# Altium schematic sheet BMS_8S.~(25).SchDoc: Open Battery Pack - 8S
size A4; Author: Morgane Vallée; Revision: 1.0; SheetNumber: 4; SheetTotal: 5
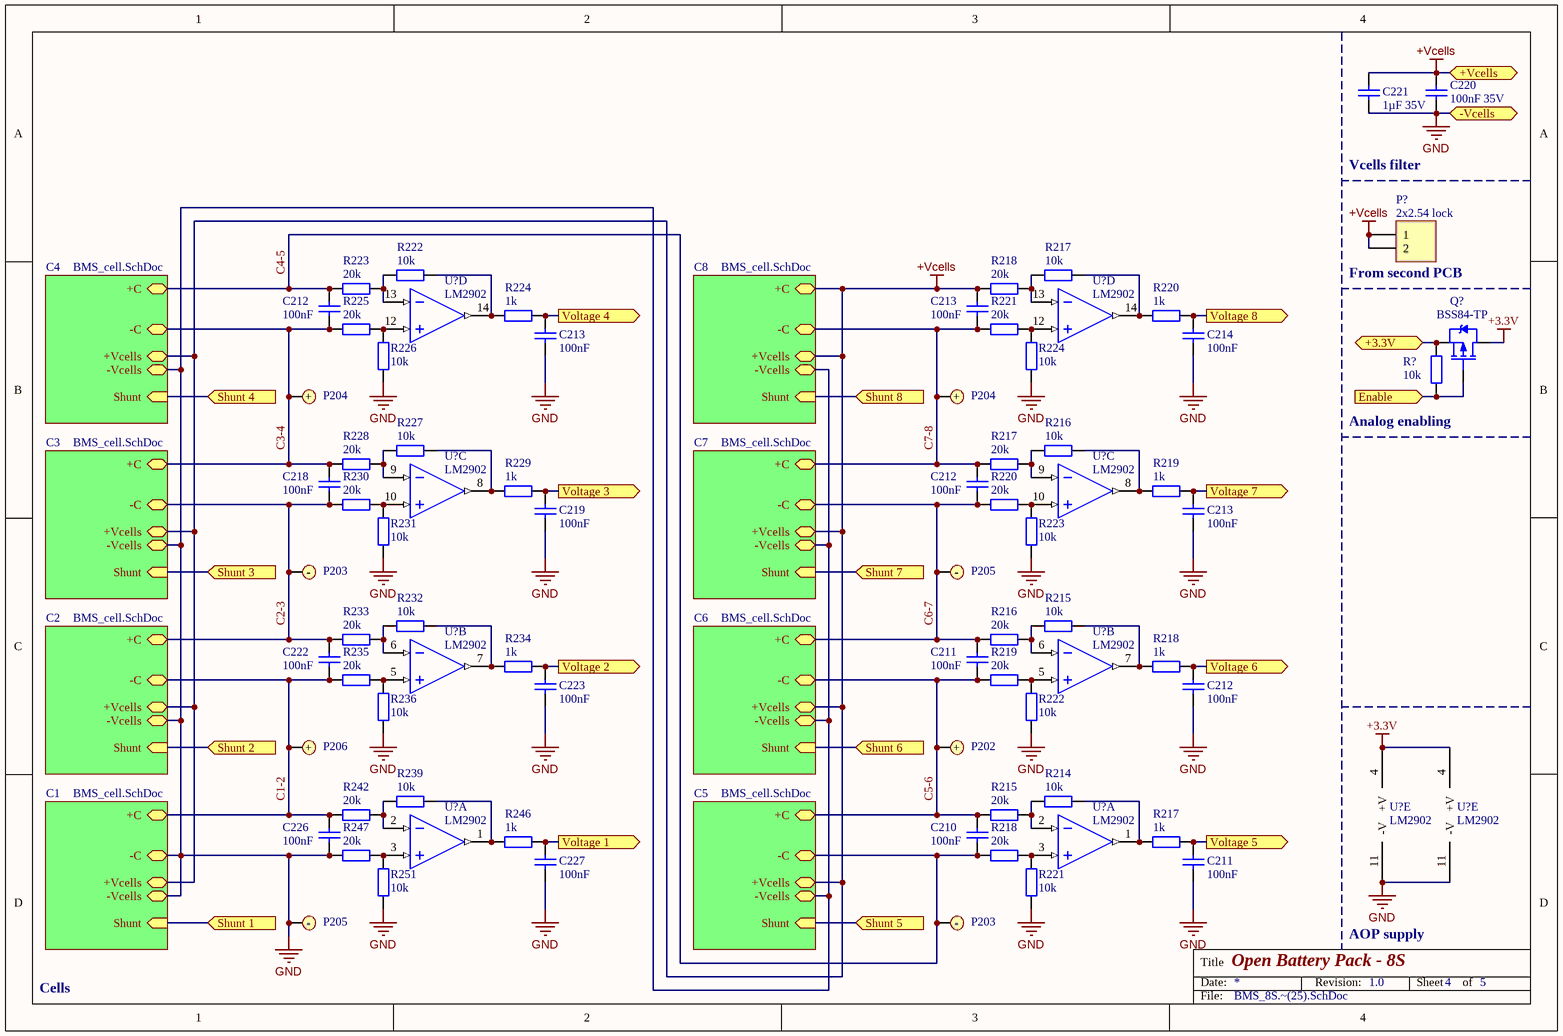
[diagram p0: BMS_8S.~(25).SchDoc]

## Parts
(Parts that share a designator on the sheet are numbered #1, #2 ... from top to bottom, then left to right.)
C210  100nF  [C0603]
C211#1  100nF  [C0603]
C211#2  100nF  [C0603]
C212#1  100nF  [C0603]
C212#2  100nF  [C0603]
C212#3  100nF  [C0603]
C213#1  100nF  [C0603]
C213#2  100nF  [C0603]
C213#3  100nF  [C0603]
C214  100nF  [C0603]
C218  100nF  [C0603]
C219  100nF  [C0603]
C220  100nF 35V  [C0603]
C221  1µF 35V  [C0805]
C222  100nF  [C0603]
C223  100nF  [C0603]
C226  100nF  [C0603]
C227  100nF  [C0603]
P202  Bat+  [Keystone 241]  (value not drawn)
P203#1  Bat-  [Keystone 2993]  (value not drawn)
P203#2  Bat-  [Keystone 2993]  (value not drawn)
P204#1  Bat+  [Keystone 241]  (value not drawn)
P204#2  Bat+  [Keystone 241]  (value not drawn)
P205#1  Bat-  [Keystone 2993]  (value not drawn)
P205#2  Bat-  [Keystone 2993]  (value not drawn)
P206  Bat+  [Keystone 241]  (value not drawn)
P?  2x2.54 lock  [MOLEX KK 0022272021]
Q?  BSS84-TP  [DIODES SOT-23-3]
R214  10k  [R0603]
R215#1  10k  [R0603]
R215#2  20k  [R0603]
R216#1  10k  [R0603]
R216#2  20k  [R0603]
R217#1  10k  [R0603]
R217#2  20k  [R0603]
R217#3  1k  [R0603]
R218#1  20k  [R0603]
R218#2  1k  [R0603]
R218#3  20k  [R0603]
R219#1  1k  [R0603]
R219#2  20k  [R0603]
R220#1  1k  [R0603]
R220#2  20k  [R0603]
R221#1  20k  [R0603]
R221#2  10k  [R0603]
R222#1  10k  [R0603]
R222#2  10k  [R0603]
R223#1  20k  [R0603]
R223#2  10k  [R0603]
R224#1  1k  [R0603]
R224#2  10k  [R0603]
R225  20k  [R0603]
R226  10k  [R0603]
R227  10k  [R0603]
R228  20k  [R0603]
R229  1k  [R0603]
R230  20k  [R0603]
R231  10k  [R0603]
R232  10k  [R0603]
R233  20k  [R0603]
R234  1k  [R0603]
R235  20k  [R0603]
R236  10k  [R0603]
R239  10k  [R0603]
R242  20k  [R0603]
R246  1k  [R0603]
R247  20k  [R0603]
R251  10k  [R0603]
R?  10k  [R0603]
U?#1  LM2902  [Atmel SO-14 14S1]  (part D of 5)
U?#2  LM2902  [Atmel SO-14 14S1]  (part D of 5)
U?#3  LM2902  [Atmel SO-14 14S1]  (part C of 5)
U?#4  LM2902  [Atmel SO-14 14S1]  (part C of 5)
U?#5  LM2902  [Atmel SO-14 14S1]  (part B of 5)
U?#6  LM2902  [Atmel SO-14 14S1]  (part B of 5)
U?#7  LM2902  [Atmel SO-14 14S1]  (part A of 5)
U?#8  LM2902  [Atmel SO-14 14S1]  (part A of 5)
U?#9  LM2902  [Atmel SO-14 14S1]  (part E of 5)
U?#10  LM2902  [Atmel SO-14 14S1]  (part E of 5)

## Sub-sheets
C1 = BMS_cell.SchDoc: -C, +C, +Vcells, -Vcells, Shunt (in)
C2 = BMS_cell.SchDoc: -C, +C, +Vcells, -Vcells, Shunt (in)
C3 = BMS_cell.SchDoc: -C, +C, +Vcells, -Vcells, Shunt (in)
C4 = BMS_cell.SchDoc: -C, +C, +Vcells, -Vcells, Shunt (in)
C5 = BMS_cell.SchDoc: -C, +C, +Vcells, -Vcells, Shunt (in)
C6 = BMS_cell.SchDoc: -C, +C, +Vcells, -Vcells, Shunt (in)
C7 = BMS_cell.SchDoc: -C, +C, +Vcells, -Vcells, Shunt (in)
C8 = BMS_cell.SchDoc: -C, +C, +Vcells, -Vcells, Shunt (in)

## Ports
+3.3V, +Vcells, -Vcells, Enable (in), Shunt 1 (in), Shunt 2 (in), Shunt 3 (in), Shunt 4 (in), Shunt 5 (in), Shunt 6 (in), Shunt 7 (in), Shunt 8 (in), Voltage 1 (out), Voltage 2 (out), Voltage 3 (out), Voltage 4 (out), Voltage 5 (out), Voltage 6 (out), Voltage 7 (out), Voltage 8 (out)

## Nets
+3.3V: Q?.3(D) U?#9.4(+V) U?#10.4(+V)
+Vcells: C213#1.1 C220.1 C221.1 P?.1 P?.2 R218#1.1 ; port +Vcells, sheet C1/+Vcells, sheet C2/+Vcells, sheet C3/+Vcells, sheet C4/+Vcells, sheet C5/+Vcells, sheet C6/+Vcells, sheet C7/+Vcells, sheet C8/+C, sheet C8/+Vcells
GND: C211#2.2 C212#3.2 C213#2.2 C213#3.2 C214.2 C219.2 C220.2 C221.2 C223.2 C226.2 C227.2 P205#2.1 R221#2.2 R222#2.2 R223#2.2 R224#2.2 R226.2 R231.2 R236.2 R247.2 R251.2 U?#9.11(-V) U?#10.11(-V) ; port -Vcells, sheet C1/-C, sheet C1/-Vcells, sheet C2/-Vcells, sheet C3/-Vcells, sheet C4/-Vcells, sheet C5/-Vcells, sheet C6/-Vcells, sheet C7/-Vcells, sheet C8/-Vcells
+3.3V: Q?.2(S) R?.2 ; port +3.3V  [a separate net that carries the same name]
C1-2: C222.2 C226.1 P206.1 R235.2 R242.1 ; sheet C1/+C, sheet C2/-C
C2-3: C218.2 C222.1 P203#1.1 R230.2 R233.1 ; sheet C2/+C, sheet C3/-C
C3-4: C212#1.2 C218.1 P204#1.1 R225.2 R228.1 ; sheet C3/+C, sheet C4/-C
C4-5: C210.2 C212#1.1 P203#2.1 R218#3.2 R223#1.1 ; sheet C4/+C, sheet C5/-C
C5-6: C210.1 C211#1.2 P202.1 R215#2.1 R219#2.2 ; sheet C5/+C, sheet C6/-C
C6-7: C211#1.1 C212#2.2 P205#1.1 R216#2.1 R220#2.2 ; sheet C6/+C, sheet C7/-C
C7-8: C212#2.1 C213#1.2 P204#2.1 R217#2.1 R221#1.2 ; sheet C7/+C, sheet C8/-C
Enable: Q?.1(G) R?.1 ; port Enable
Shunt 1: port Shunt 1, sheet C1/Shunt
Shunt 2: port Shunt 2, sheet C2/Shunt
Shunt 3: port Shunt 3, sheet C3/Shunt
Shunt 4: port Shunt 4, sheet C4/Shunt
Shunt 5: port Shunt 5, sheet C5/Shunt
Shunt 6: port Shunt 6, sheet C6/Shunt
Shunt 7: port Shunt 7, sheet C7/Shunt
Shunt 8: port Shunt 8, sheet C8/Shunt
Voltage 1: C227.1 R246.1 ; port Voltage 1
Voltage 2: C223.1 R234.1 ; port Voltage 2
Voltage 3: C219.1 R229.1 ; port Voltage 3
Voltage 4: C213#2.1 R224#1.1 ; port Voltage 4
Voltage 5: C211#2.1 R217#3.1 ; port Voltage 5
Voltage 6: C212#3.1 R218#2.1 ; port Voltage 6
Voltage 7: C213#3.1 R219#1.1 ; port Voltage 7
Voltage 8: C214.1 R220#1.1 ; port Voltage 8
NetR214_1: R214.1 R215#2.2 U?#8.2(IN-)
NetR214_2: R214.2 R217#3.2 U?#8.1(OUT)
NetR215#1_1: R215#1.1 R216#2.2 U?#6.6(IN-)
NetR215#1_2: R215#1.2 R218#2.2 U?#6.7(OUT)
NetR216#1_1: R216#1.1 R217#2.2 U?#4.9(IN-)
NetR216#1_2: R216#1.2 R219#1.2 U?#4.8(OUT)
NetR217#1_1: R217#1.1 R218#1.2 U?#2.13(IN-)
NetR217#1_2: R217#1.2 R220#1.2 U?#2.14(OUT)
NetR218#3_1: R218#3.1 R221#2.1 U?#8.3(IN+)
NetR219#2_1: R219#2.1 R222#2.1 U?#6.5(IN+)
NetR220#2_1: R220#2.1 R223#2.1 U?#4.10(IN+)
NetR221#1_1: R221#1.1 R224#2.1 U?#2.12(IN+)
NetR222#1_1: R222#1.1 R223#1.2 U?#1.13(IN-)
NetR222#1_2: R222#1.2 R224#1.2 U?#1.14(OUT)
NetR225_1: R225.1 R226.1 U?#1.12(IN+)
NetR227_1: R227.1 R228.2 U?#3.9(IN-)
NetR227_2: R227.2 R229.2 U?#3.8(OUT)
NetR230_1: R230.1 R231.1 U?#3.10(IN+)
NetR232_1: R232.1 R233.2 U?#5.6(IN-)
NetR232_2: R232.2 R234.2 U?#5.7(OUT)
NetR235_1: R235.1 R236.1 U?#5.5(IN+)
NetR239_1: R239.1 R242.2 U?#7.2(IN-)
NetR239_2: R239.2 R246.2 U?#7.1(OUT)
NetR247_1: R247.1 R251.1 U?#7.3(IN+)

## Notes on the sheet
- Vcells filter
- (near P?) From second PCB
- Analog enabling
- AOP supply
- Cells

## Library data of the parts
C210 C211#1 C211#2 C212#1-C212#3 C213#1-C213#3 C214 C218-C223 C226 C227 = Cap: Capacitor
P202 P204#1 P204#2 P206 = Bat+: Battery contact +
P203#1 P203#2 P205#1 P205#2 = Bat-: Battery contact -
P? = Header 2: Header, 2-Pin
Q? = MOSFET_P
R214 R215#1 R215#2 R216#1 R216#2 R217#1-R217#3 R218#1-R218#3 R219#1 R219#2 R220#1 R220#2 R221#1 R221#2 R222#1 R222#2 R223#1 R223#2 R224#1 R224#2 R225-R236 R239 R242 R246 R247 R251 R? = Res2: Resistor
U?#1-U?#10 = LM2902: Low-power quad operational amplifiers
